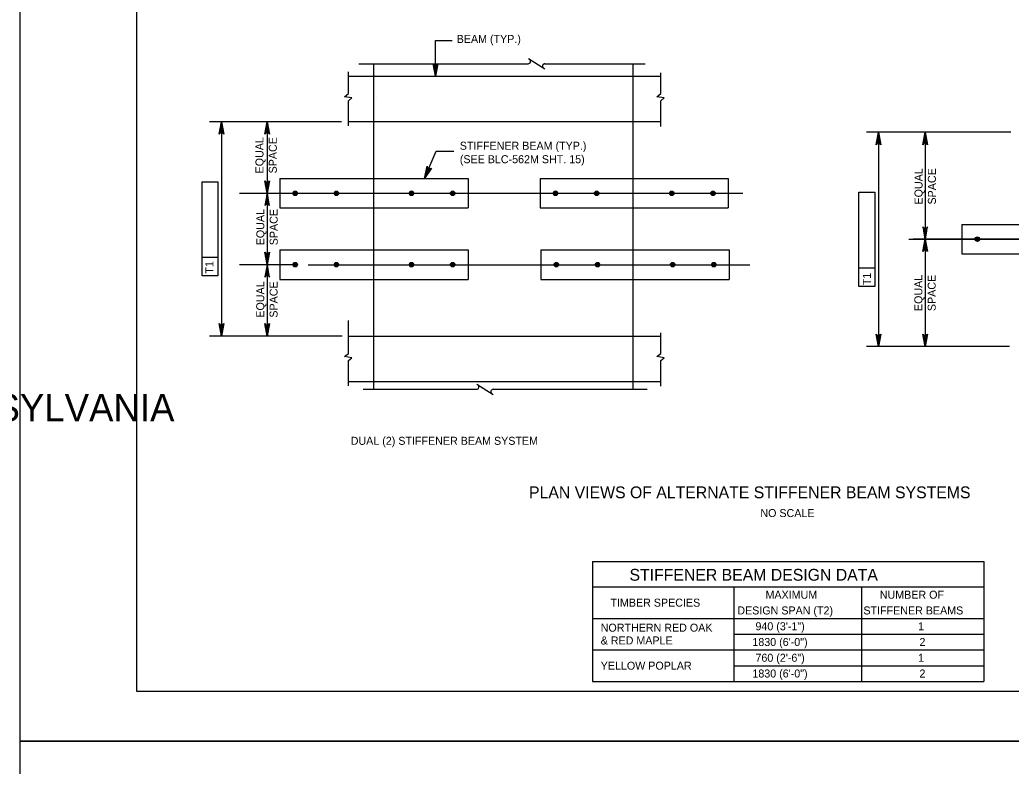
# Model space of a CAD drawing. Extents: x -13 to 81, y -176 to 0.
# Drawn here: x 34 to 48.87, y -110.38 to -99.19 of the extents above; entities that cross this region are included whole.
import ezdxf

# ---------------------------------------------------------------- set-up
doc = ezdxf.new("R2010")
doc.units = 0
for name, color, linetype in [('Level 1', 7, 'Continuous'), ('Level 10', 7, 'Continuous'), ('Level 2', 7, 'Continuous'), ('Level 3', 7, 'Continuous'), ('Level 4', 7, 'Continuous'), ('Level 63', 7, 'Continuous'), ('Level 8', 7, 'Continuous')]:
    doc.layers.add(name, color=color, linetype=linetype)

msp = doc.modelspace()

# ---------------------------------------------------------------- linework, layer by layer
at = {"layer": 'Level 1'}
msp.add_lwpolyline([(35.75, -109.25), (67.25, -109.25), (67.25, -88.75), (35.75, -88.75)], close=True, dxfattribs=at)
at = {"layer": 'Level 10'}
for p, q in [((42.591, -107.307), (42.591, -109.105)), ((42.591, -107.307), (48.457, -107.307)), ((48.457, -107.307), (48.457, -109.105)), ((42.591, -107.688), (48.457, -107.688)), ((44.71, -107.688), (44.71, -109.105)), ((46.621, -107.688), (46.621, -109.105)), ((42.591, -108.161), (48.457, -108.161)), ((44.71, -108.397), (48.457, -108.397)), ((42.591, -108.633), (48.457, -108.633)), ((44.71, -108.869), (48.457, -108.869)), ((42.591, -109.105), (48.457, -109.105))]:
    msp.add_line(p, q, dxfattribs=at)
at = {"layer": 'Level 2'}
for p, q in [((39.311, -104.724), (39.311, -99.846)), ((43.201, -104.724), (43.201, -99.846))]:
    msp.add_line(p, q, dxfattribs=at)
at = {"layer": 'Level 3'}
for p, q in [((39.082, -99.846), (41.624, -99.846)), ((41.627, -99.769), (41.873, -99.924)), ((41.872, -99.846), (43.38, -99.846)), ((38.931, -100.293), (38.931, -99.969)), ((38.931, -100.032), (43.614, -100.032)), ((43.614, -100.293), (43.614, -99.984)), ((38.87, -100.341), (38.931, -100.293)), ((38.98, -100.358), (38.87, -100.341)), ((38.931, -100.401), (38.98, -100.358)), ((43.553, -100.341), (43.614, -100.293)), ((43.663, -100.358), (43.553, -100.341)), ((43.614, -100.401), (43.663, -100.358)), ((38.931, -100.778), (38.931, -100.401)), ((43.614, -100.786), (43.614, -100.401)), ((43.614, -100.716), (38.931, -100.716)), ((37.9, -101.567), (37.9, -102.008)), ((37.9, -101.567), (40.723, -101.567)), ((40.723, -101.567), (40.723, -102.008)), ((41.803, -101.567), (41.803, -102.008)), ((41.803, -101.567), (44.626, -101.567)), ((44.626, -101.567), (44.626, -102.008)), ((39.308, -101.787), (39.308, -101.787)), ((37.9, -102.008), (40.723, -102.008)), ((41.803, -102.008), (44.626, -102.008)), ((48.13, -102.255), (50.953, -102.255)), ((48.13, -102.255), (48.13, -102.696)), ((37.9, -102.637), (40.723, -102.637)), ((37.9, -102.637), (37.9, -103.078)), ((40.723, -102.637), (40.723, -103.078)), ((41.816, -102.637), (44.639, -102.637)), ((41.816, -102.637), (41.816, -103.078)), ((44.639, -102.637), (44.639, -103.078)), ((48.13, -102.696), (50.953, -102.696)), ((39.308, -102.857), (39.308, -102.857)), ((37.9, -103.078), (40.723, -103.078)), ((41.816, -103.078), (44.639, -103.078)), ((38.931, -104.188), (38.931, -103.697)), ((38.931, -104.188), (38.931, -103.864)), ((38.931, -103.927), (43.614, -103.927)), ((43.614, -104.188), (43.614, -103.879)), ((38.87, -104.236), (38.931, -104.188)), ((43.553, -104.236), (43.614, -104.188)), ((38.98, -104.253), (38.87, -104.236)), ((38.931, -104.296), (38.98, -104.253)), ((38.931, -104.673), (38.931, -104.296)), ((43.663, -104.253), (43.553, -104.236)), ((43.614, -104.296), (43.663, -104.253)), ((43.614, -104.681), (43.614, -104.296)), ((43.614, -104.612), (38.931, -104.612)), ((40.853, -104.647), (41.099, -104.802)), ((39.148, -104.724), (40.85, -104.724)), ((41.098, -104.724), (43.407, -104.724))]:
    msp.add_line(p, q, dxfattribs=at)
for centre, radius in [((38.13, -101.788), 0.0333), ((38.13, -101.788), 0.0295), ((38.13, -101.788), 0.025), ((38.13, -101.788), 0.0167), ((38.13, -101.788), 0.00833), ((38.748, -101.788), 0.0333), ((38.748, -101.788), 0.0295), ((38.748, -101.788), 0.025), ((38.748, -101.788), 0.0167), ((38.748, -101.788), 0.00833), ((39.874, -101.788), 0.0333), ((39.874, -101.788), 0.0295), ((39.874, -101.788), 0.025), ((39.874, -101.788), 0.0167), ((39.874, -101.788), 0.00833), ((40.492, -101.788), 0.0333), ((40.492, -101.788), 0.0295), ((40.492, -101.788), 0.025), ((40.492, -101.788), 0.0167), ((40.492, -101.788), 0.00833), ((42.034, -101.788), 0.0333), ((42.034, -101.788), 0.0295), ((42.034, -101.788), 0.025), ((42.034, -101.788), 0.0167), ((42.034, -101.788), 0.00833), ((42.652, -101.788), 0.0333), ((42.652, -101.788), 0.0295), ((42.652, -101.788), 0.025), ((42.652, -101.788), 0.0167), ((42.652, -101.788), 0.00833), ((43.778, -101.788), 0.0333), ((43.778, -101.788), 0.0295), ((43.778, -101.788), 0.025), ((43.778, -101.788), 0.0167), ((43.778, -101.788), 0.00833), ((44.396, -101.788), 0.0333), ((44.396, -101.788), 0.0295), ((44.396, -101.788), 0.025), ((44.396, -101.788), 0.0167), ((44.396, -101.788), 0.00833), ((48.361, -102.476), 0.0333), ((48.361, -102.476), 0.0295), ((48.361, -102.476), 0.025), ((48.361, -102.476), 0.0167), ((48.361, -102.476), 0.00833), ((38.13, -102.858), 0.0333), ((38.13, -102.858), 0.0295), ((38.13, -102.858), 0.025), ((38.13, -102.858), 0.0167), ((38.13, -102.858), 0.00833), ((38.748, -102.858), 0.0333), ((38.748, -102.858), 0.0295), ((38.748, -102.858), 0.025), ((38.748, -102.858), 0.0167), ((38.748, -102.858), 0.00833), ((39.874, -102.858), 0.0333), ((39.874, -102.858), 0.0295), ((39.874, -102.858), 0.025), ((39.874, -102.858), 0.0167), ((39.874, -102.858), 0.00833), ((40.492, -102.858), 0.0333), ((40.492, -102.858), 0.0295), ((40.492, -102.858), 0.025), ((40.492, -102.858), 0.0167), ((40.492, -102.858), 0.00833), ((42.047, -102.858), 0.0333), ((42.047, -102.858), 0.0295), ((42.047, -102.858), 0.025), ((42.047, -102.858), 0.0167), ((42.047, -102.858), 0.00833), ((42.665, -102.858), 0.0333), ((42.665, -102.858), 0.0295), ((42.665, -102.858), 0.025), ((42.665, -102.858), 0.0167), ((42.665, -102.858), 0.00833), ((43.791, -102.858), 0.0333), ((43.791, -102.858), 0.0295), ((43.791, -102.858), 0.025), ((43.791, -102.858), 0.0167), ((43.791, -102.858), 0.00833), ((44.409, -102.858), 0.0333), ((44.409, -102.858), 0.0295), ((44.409, -102.858), 0.025), ((44.409, -102.858), 0.0167), ((44.409, -102.858), 0.00833)]:
    msp.add_circle(centre, radius, dxfattribs=at)
for centre, start, end in [((41.624, -99.81), 270, 60), ((41.876, -99.883), 95.3286, 237.8672), ((40.85, -104.688), 270, 60), ((41.102, -104.761), 95.3286, 237.8672)]:
    msp.add_arc(centre, 0.0364, start, end, dxfattribs=at)
at = {"layer": 'Level 4'}
for p, q in [((40.235, -99.498), (40.485, -99.498)), ((38.824, -100.716), (36.845, -100.716)), ((37.025, -100.716), (37.025, -103.927)), ((38.222, -100.716), (37.619, -100.716)), ((37.708, -100.716), (37.708, -101.787)), ((48.861, -100.873), (46.696, -100.873)), ((46.876, -100.873), (46.876, -104.084)), ((47.576, -100.873), (47.576, -102.475)), ((40.242, -101.155), (40.508, -101.155)), ((36.733, -101.615), (36.969, -101.615)), ((36.733, -103.027), (36.733, -101.615)), ((36.969, -101.615), (36.969, -103.027)), ((37.296, -101.787), (38.748, -101.787)), ((37.634, -101.787), (44.844, -101.787)), ((37.708, -101.787), (37.708, -102.739)), ((46.585, -101.772), (46.821, -101.772)), ((46.585, -102.885), (46.585, -101.772)), ((46.821, -101.772), (46.821, -103.184)), ((47.332, -102.475), (49.114, -102.475)), ((49.078, -102.475), (47.396, -102.475)), ((47.576, -102.475), (47.576, -104.084)), ((36.969, -102.751), (36.733, -102.751)), ((37.296, -102.857), (38.168, -102.857)), ((38.326, -102.858), (44.949, -102.858)), ((46.585, -103.184), (46.585, -102.885)), ((36.969, -103.027), (36.733, -103.027)), ((37.71, -102.975), (37.71, -103.927)), ((46.821, -102.908), (46.585, -102.908)), ((46.821, -103.184), (46.585, -103.184)), ((38.833, -103.927), (36.845, -103.927)), ((37.97, -103.927), (37.635, -103.927)), ((48.843, -104.084), (46.696, -104.084))]:
    msp.add_line(p, q, dxfattribs=at)
for points in [[(40.235, -100.032), (40.235, -99.498)], [(40.235, -100.032), (40.2, -99.845), (40.21, -99.859), (40.222, -99.867), (40.235, -99.869), (40.247, -99.867), (40.26, -99.859), (40.27, -99.845), (40.235, -100.032), (40.26, -99.859), (40.247, -99.867), (40.235, -100.032), (40.235, -99.869), (40.222, -99.867), (40.235, -100.032), (40.21, -99.859)], [(37.025, -100.716), (37.06, -100.903), (37.05, -100.889), (37.037, -100.881), (37.025, -100.879), (37.012, -100.881), (37, -100.889), (36.99, -100.903), (37.025, -100.716), (37, -100.889), (37.012, -100.881), (37.025, -100.716), (37.025, -100.879), (37.037, -100.881), (37.025, -100.716), (37.05, -100.889)], [(37.708, -100.716), (37.743, -100.903), (37.733, -100.889), (37.72, -100.881), (37.708, -100.879), (37.695, -100.881), (37.683, -100.889), (37.673, -100.903), (37.708, -100.716), (37.683, -100.889), (37.695, -100.881), (37.708, -100.716), (37.708, -100.879), (37.72, -100.881), (37.708, -100.716), (37.733, -100.889)], [(46.876, -100.873), (46.911, -101.06), (46.901, -101.045), (46.889, -101.038), (46.876, -101.036), (46.864, -101.038), (46.851, -101.045), (46.841, -101.06), (46.876, -100.873), (46.851, -101.045), (46.864, -101.038), (46.876, -100.873), (46.876, -101.036), (46.889, -101.038), (46.876, -100.873), (46.901, -101.045)], [(47.576, -100.873), (47.611, -101.06), (47.601, -101.045), (47.589, -101.038), (47.576, -101.036), (47.564, -101.038), (47.551, -101.045), (47.541, -101.06), (47.576, -100.873), (47.551, -101.045), (47.564, -101.038), (47.576, -100.873), (47.576, -101.036), (47.589, -101.038), (47.576, -100.873), (47.601, -101.045)], [(40.069, -101.567), (40.242, -101.155)], [(40.069, -101.567), (40.109, -101.382), (40.113, -101.399), (40.121, -101.411), (40.132, -101.417), (40.144, -101.42), (40.159, -101.418), (40.173, -101.409), (40.069, -101.567), (40.159, -101.418), (40.144, -101.42), (40.069, -101.567), (40.132, -101.417), (40.121, -101.411), (40.069, -101.567), (40.113, -101.399)], [(37.708, -101.787), (37.673, -101.6), (37.683, -101.614), (37.695, -101.622), (37.708, -101.624), (37.72, -101.622), (37.733, -101.614), (37.743, -101.6), (37.708, -101.787), (37.733, -101.614), (37.72, -101.622), (37.708, -101.787), (37.708, -101.624), (37.695, -101.622), (37.708, -101.787), (37.683, -101.614)], [(37.708, -101.787), (37.673, -101.973), (37.683, -101.959), (37.695, -101.951), (37.708, -101.949), (37.72, -101.951), (37.733, -101.959), (37.743, -101.973), (37.708, -101.787), (37.733, -101.959), (37.72, -101.951), (37.708, -101.787), (37.708, -101.949), (37.695, -101.951), (37.708, -101.787), (37.683, -101.959)], [(47.576, -102.475), (47.611, -102.288), (47.601, -102.303), (47.589, -102.31), (47.576, -102.312), (47.564, -102.31), (47.551, -102.303), (47.541, -102.288), (47.576, -102.475), (47.551, -102.303), (47.564, -102.31), (47.576, -102.475), (47.576, -102.312), (47.589, -102.31), (47.576, -102.475), (47.601, -102.303)], [(47.576, -102.475), (47.611, -102.661), (47.601, -102.647), (47.589, -102.639), (47.576, -102.637), (47.564, -102.639), (47.551, -102.647), (47.541, -102.661), (47.576, -102.475), (47.551, -102.647), (47.564, -102.639), (47.576, -102.475), (47.576, -102.637), (47.589, -102.639), (47.576, -102.475), (47.601, -102.647)], [(37.71, -102.857), (37.675, -102.67), (37.685, -102.685), (37.698, -102.692), (37.71, -102.694), (37.723, -102.692), (37.735, -102.685), (37.745, -102.67), (37.71, -102.857), (37.735, -102.685), (37.723, -102.692), (37.71, -102.857), (37.71, -102.694), (37.698, -102.692), (37.71, -102.857), (37.685, -102.685)], [(37.71, -102.857), (37.675, -103.043), (37.685, -103.029), (37.698, -103.021), (37.71, -103.019), (37.723, -103.021), (37.735, -103.029), (37.745, -103.043), (37.71, -102.857), (37.735, -103.029), (37.723, -103.021), (37.71, -102.857), (37.71, -103.019), (37.698, -103.021), (37.71, -102.857), (37.685, -103.029)], [(37.025, -103.927), (36.99, -103.74), (37, -103.755), (37.012, -103.762), (37.025, -103.764), (37.037, -103.762), (37.05, -103.755), (37.06, -103.74), (37.025, -103.927), (37.05, -103.755), (37.037, -103.762), (37.025, -103.927), (37.025, -103.764), (37.012, -103.762), (37.025, -103.927), (37, -103.755)], [(37.71, -103.927), (37.675, -103.74), (37.685, -103.755), (37.698, -103.762), (37.71, -103.764), (37.723, -103.762), (37.735, -103.755), (37.745, -103.74), (37.71, -103.927), (37.735, -103.755), (37.723, -103.762), (37.71, -103.927), (37.71, -103.764), (37.698, -103.762), (37.71, -103.927), (37.685, -103.755)], [(46.876, -104.084), (46.841, -103.897), (46.851, -103.911), (46.864, -103.919), (46.876, -103.921), (46.889, -103.919), (46.901, -103.911), (46.911, -103.897), (46.876, -104.084), (46.901, -103.911), (46.889, -103.919), (46.876, -104.084), (46.876, -103.921), (46.864, -103.919), (46.876, -104.084), (46.851, -103.911)], [(47.576, -104.084), (47.541, -103.897), (47.551, -103.911), (47.564, -103.919), (47.576, -103.921), (47.589, -103.919), (47.601, -103.911), (47.611, -103.897), (47.576, -104.084), (47.601, -103.911), (47.589, -103.919), (47.576, -104.084), (47.576, -103.921), (47.564, -103.919), (47.576, -104.084), (47.551, -103.911)]]:
    msp.add_lwpolyline(points, dxfattribs=at)
for points in [[(40.235, -100.032), (40.236, -100.027), (40.233, -100.027)], [(46.856, -100.993), (46.896, -100.993), (46.876, -100.873)], [(47.556, -100.993), (47.596, -100.993), (47.576, -100.873)], [(40.069, -101.567), (40.072, -101.563), (40.07, -101.562)], [(47.556, -102.355), (47.596, -102.355), (47.576, -102.475)], [(47.556, -102.595), (47.596, -102.595), (47.576, -102.475)], [(37.688, -102.739), (37.728, -102.739), (37.708, -102.857)], [(37.691, -102.975), (37.73, -102.975), (37.71, -102.857)], [(37.005, -103.807), (37.045, -103.807), (37.025, -103.927)], [(37.691, -103.809), (37.73, -103.809), (37.71, -103.927)], [(46.856, -103.964), (46.896, -103.964), (46.876, -104.084)], [(47.556, -103.956), (47.596, -103.956), (47.576, -104.076)]]:
    msp.add_lwpolyline(points, close=True, dxfattribs=at)
at = {"layer": 'Level 63'}
for points in [[(34, -110), (68, -110), (68, -88), (34, -88)], [(34, -132), (68, -132), (68, -110), (34, -110)]]:
    msp.add_lwpolyline(points, close=True, dxfattribs=at)
at = {"layer": 'Level 8'}
for p, q in [((39.342, -100.347), (39.342, -100.347)), ((39.343, -100.346), (39.343, -100.346)), ((39.308, -101.787), (39.308, -101.787)), ((39.308, -102.857), (39.308, -102.857)), ((39.311, -104.243), (39.311, -104.243))]:
    msp.add_line(p, q, dxfattribs=at)

# ---------------------------------------------------------------- texts
at = {"layer": 'Level 1'}
msp.add_text('COMMONWEALTH OF PENNSYLVANIA', height=0.41048, dxfattribs=at).set_placement((26.194, -105.207))
at = {"layer": 'Level 4'}
for s, height, p in [('BEAM (TYP.)', 0.12, (40.552, -99.534)), ('STIFFENER BEAM (TYP.)', 0.12, (40.599, -101.135)), ('(SEE BLC-562M SHT. 15)', 0.12, (40.599, -101.337)), ('DUAL (2) STIFFENER BEAM SYSTEM', 0.12, (38.963, -105.558)), ('PLAN VIEWS OF ALTERNATE STIFFENER BEAM SYSTEMS', 0.17717, (41.637, -106.359)), ('NO SCALE', 0.12, (45.107, -106.641)), ('STIFFENER BEAM DESIGN DATA', 0.17717, (43.144, -107.595)), ('MAXIMUM', 0.12, (45.184, -107.865)), ('NUMBER OF ', 0.12, (46.898, -107.865)), ('TIMBER SPECIES', 0.12, (42.858, -107.984)), ('DESIGN SPAN (T2)', 0.12, (44.761, -108.101)), ('STIFFENER BEAMS', 0.12, (46.652, -108.101)), ('NORTHERN RED OAK', 0.12, (42.712, -108.359)), ('940 (3\'-1")', 0.12, (45.033, -108.338)), ('1', 0.12, (47.472, -108.338)), ('& RED MAPLE', 0.12, (42.712, -108.551)), ('1830 (6\'-0")', 0.12, (44.987, -108.574)), ('2', 0.12, (47.493, -108.574)), ('760 (2\'-6")', 0.12, (45.033, -108.81)), ('YELLOW POPLAR', 0.12, (42.712, -108.929)), ('1', 0.12, (47.472, -108.81)), ('1830 (6\'-0")', 0.12, (44.987, -109.046)), ('2', 0.12, (47.493, -109.046))]:
    msp.add_text(s, height=height, dxfattribs=at).set_placement(p)
for p in [(36.903, -102.992), (46.764, -103.166)]:
    msp.add_text('T1', height=0.12, rotation=90, dxfattribs=at).set_placement(p)
at = {"layer": 'Level 8'}
for s, p in [('EQUAL ', (37.654, -101.49)), ('SPACE', (37.854, -101.49)), ('EQUAL ', (47.539, -101.956)), ('SPACE', (47.739, -101.956)), ('EQUAL ', (37.667, -102.567)), ('SPACE', (37.867, -102.567)), ('EQUAL ', (47.536, -103.553)), ('SPACE', (47.736, -103.554)), ('EQUAL ', (37.666, -103.652)), ('SPACE', (37.866, -103.652))]:
    msp.add_text(s, height=0.12, rotation=89.9708, dxfattribs=at).set_placement(p)

doc.saveas('drawing.dxf')
